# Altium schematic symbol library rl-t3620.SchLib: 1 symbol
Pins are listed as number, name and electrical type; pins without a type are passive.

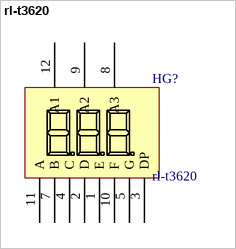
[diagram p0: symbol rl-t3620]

## rl-t3620
designator HG?
footprint PCBComponent_1
pins: 1 E, 2 D, 3 DP, 4 C, 5 G, 7 B, 8 A3, 9 A2, 10 F, 11 A, 12 A1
